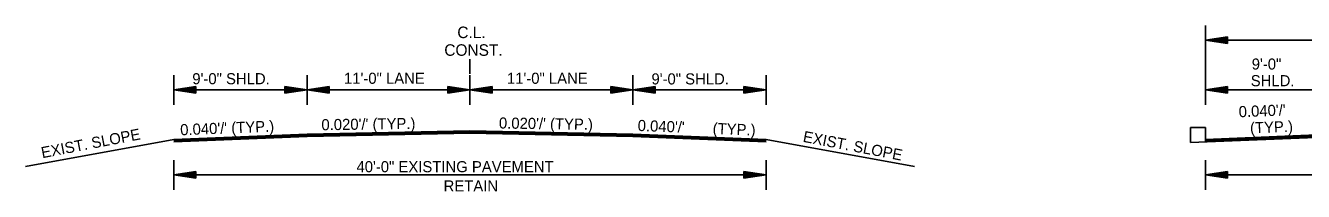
# Model space of a CAD drawing. Extents: x 545241 to 1930787, y -1971772 to 596640.
# Drawn here: x 546787 to 547650, y -1963232 to -1963120 of the extents above; entities that cross this region are included whole.
import ezdxf

# ---------------------------------------------------------------- set-up
doc = ezdxf.new("R2010")
doc.units = 0
doc.layers.add('R_Border', color=7, linetype='Continuous')
doc.layers.add('R_Draft', color=7, linetype='Continuous')

msp = doc.modelspace()

# ---------------------------------------------------------------- linework, layer by layer
at = {"layer": 'R_Border'}
for p, q in [((546977.57, -1963192.94), (546887.57, -1963196.54)), ((546977.57, -1963193.24), (546887.57, -1963196.84)), ((546977.57, -1963193.54), (546887.57, -1963197.14)), ((546977.57, -1963193.84), (546887.57, -1963197.44)), ((546977.57, -1963194.14), (546887.57, -1963197.74)), ((546977.57, -1963194.44), (546887.57, -1963198.04)), ((546977.57, -1963194.61), (546887.57, -1963198.21)), ((547197.57, -1963192.94), (547287.57, -1963196.54)), ((547197.57, -1963193.24), (547287.57, -1963196.84)), ((547197.57, -1963193.54), (547287.57, -1963197.14)), ((547197.57, -1963193.84), (547287.57, -1963197.44)), ((547197.57, -1963194.14), (547287.57, -1963197.74)), ((547197.57, -1963194.44), (547287.57, -1963198.04)), ((547197.57, -1963194.61), (547287.57, -1963198.21)), ((547573.95, -1963188.63), (547573.94, -1963198.62)), ((547674.12, -1963194.61), (547573.94, -1963198.61)), ((547584.12, -1963188.63), (547573.95, -1963188.63)), ((547584.12, -1963198.04), (547584.12, -1963188.63)), ((547674.12, -1963192.94), (547584.12, -1963196.54)), ((547674.12, -1963193.24), (547584.12, -1963196.84)), ((547674.12, -1963193.54), (547584.12, -1963197.14)), ((547674.12, -1963193.84), (547584.12, -1963197.44)), ((547674.12, -1963194.14), (547584.12, -1963197.74)), ((547674.12, -1963194.44), (547584.12, -1963198.04))]:
    msp.add_line(p, q, dxfattribs=at)
at = {"layer": 'R_Draft'}
for p, q in [((547584.12, -1963173.13), (547584.12, -1963119.59)), ((547599.12, -1963127.34), (547584.12, -1963129.59)), ((547584.12, -1963129.59), (547984.12, -1963129.59)), ((547599.12, -1963131.84), (547584.12, -1963129.59)), ((547599.12, -1963127.72), (547586.63, -1963129.59)), ((547599.12, -1963131.47), (547586.63, -1963129.59)), ((547599.12, -1963128.1), (547589.21, -1963129.59)), ((547599.12, -1963131.09), (547589.21, -1963129.59)), ((547599.12, -1963128.48), (547591.7, -1963129.59)), ((547599.12, -1963130.71), (547591.7, -1963129.59)), ((547599.12, -1963128.86), (547594.25, -1963129.59)), ((547599.12, -1963130.32), (547594.25, -1963129.59)), ((547599.12, -1963129.24), (547596.75, -1963129.59)), ((547599.12, -1963129.95), (547596.75, -1963129.59)), ((547599.12, -1963131.84), (547599.12, -1963127.34)), ((547087.57, -1963152.36), (547087.57, -1963142.36)), ((546887.57, -1963173.13), (546887.57, -1963153.13)), ((546902.57, -1963160.88), (546887.57, -1963163.13)), ((546902.57, -1963161.26), (546890.07, -1963163.13)), ((546902.57, -1963160.88), (546902.57, -1963165.38)), ((546962.57, -1963160.88), (546977.57, -1963163.13)), ((546962.57, -1963165.38), (546962.57, -1963160.88)), ((546962.57, -1963161.26), (546975.06, -1963163.13)), ((546977.57, -1963173.13), (546977.57, -1963153.24)), ((546992.57, -1963160.88), (546977.57, -1963163.13)), ((546992.57, -1963161.26), (546980.07, -1963163.13)), ((546992.57, -1963165.38), (546992.57, -1963160.88)), ((547072.57, -1963160.88), (547087.57, -1963163.13)), ((547072.57, -1963160.88), (547072.57, -1963165.38)), ((547072.57, -1963161.26), (547085.06, -1963163.13)), ((547087.57, -1963173.13), (547087.57, -1963153.24)), ((547102.57, -1963160.88), (547087.57, -1963163.13)), ((547102.57, -1963161.26), (547090.07, -1963163.13)), ((547102.57, -1963160.88), (547102.57, -1963165.38)), ((547182.57, -1963160.88), (547197.57, -1963163.13)), ((547182.57, -1963165.38), (547182.57, -1963160.88)), ((547182.57, -1963161.26), (547195.06, -1963163.13)), ((547197.57, -1963173.13), (547197.57, -1963153.24)), ((547212.57, -1963160.88), (547197.57, -1963163.13)), ((547212.57, -1963161.26), (547200.07, -1963163.13)), ((547212.57, -1963165.38), (547212.57, -1963160.88)), ((547272.57, -1963160.88), (547287.57, -1963163.13)), ((547272.57, -1963160.88), (547272.57, -1963165.38)), ((547272.57, -1963161.26), (547285.06, -1963163.13)), ((547287.57, -1963173.13), (547287.57, -1963153.13)), ((547599.12, -1963160.88), (547584.12, -1963163.13)), ((547599.12, -1963161.26), (547586.63, -1963163.13)), ((547599.12, -1963160.88), (547599.12, -1963165.38)), ((546977.57, -1963163.13), (546887.57, -1963163.13)), ((546902.57, -1963165.38), (546887.57, -1963163.13)), ((546902.57, -1963165.01), (546890.07, -1963163.13)), ((546902.57, -1963161.64), (546892.65, -1963163.13)), ((546902.57, -1963164.62), (546892.65, -1963163.13)), ((546902.57, -1963162.01), (546895.15, -1963163.13)), ((546902.57, -1963164.25), (546895.15, -1963163.13)), ((546902.57, -1963162.4), (546897.69, -1963163.13)), ((546902.57, -1963163.87), (546897.69, -1963163.13)), ((546902.57, -1963162.78), (546900.2, -1963163.13)), ((546902.57, -1963163.48), (546900.2, -1963163.13)), ((546962.57, -1963161.64), (546972.48, -1963163.13)), ((546962.57, -1963162.01), (546969.99, -1963163.13)), ((546962.57, -1963162.4), (546967.44, -1963163.13)), ((546962.57, -1963162.78), (546964.94, -1963163.13)), ((546962.57, -1963165.38), (546977.57, -1963163.13)), ((546962.57, -1963163.86), (546967.44, -1963163.13)), ((546962.57, -1963164.62), (546972.48, -1963163.13)), ((546962.57, -1963165.01), (546975.06, -1963163.13)), ((546962.57, -1963164.25), (546969.99, -1963163.13)), ((546962.57, -1963163.48), (546964.94, -1963163.13)), ((546992.57, -1963165.38), (546977.57, -1963163.13)), ((546977.57, -1963163.13), (547087.57, -1963163.13)), ((546992.57, -1963165.01), (546980.07, -1963163.13)), ((546992.57, -1963161.64), (546982.65, -1963163.13)), ((546992.57, -1963164.62), (546982.65, -1963163.13)), ((546992.57, -1963162.01), (546985.15, -1963163.13)), ((546992.57, -1963164.25), (546985.15, -1963163.13)), ((546992.57, -1963162.4), (546987.69, -1963163.13)), ((546992.57, -1963163.86), (546987.69, -1963163.13)), ((546992.57, -1963162.78), (546990.2, -1963163.13)), ((546992.57, -1963163.48), (546990.2, -1963163.13)), ((547072.57, -1963161.64), (547082.48, -1963163.13)), ((547072.57, -1963162.01), (547079.99, -1963163.13)), ((547072.57, -1963162.4), (547077.44, -1963163.13)), ((547072.57, -1963162.78), (547074.94, -1963163.13)), ((547072.57, -1963165.38), (547087.57, -1963163.13)), ((547072.57, -1963163.87), (547077.44, -1963163.13)), ((547072.57, -1963164.62), (547082.48, -1963163.13)), ((547072.57, -1963165.01), (547085.06, -1963163.13)), ((547072.57, -1963164.25), (547079.99, -1963163.13)), ((547072.57, -1963163.48), (547074.94, -1963163.13)), ((547197.57, -1963163.13), (547087.57, -1963163.13)), ((547102.57, -1963165.38), (547087.57, -1963163.13)), ((547102.57, -1963165.01), (547090.07, -1963163.13)), ((547102.57, -1963161.64), (547092.65, -1963163.13)), ((547102.57, -1963164.62), (547092.65, -1963163.13)), ((547102.57, -1963162.01), (547095.15, -1963163.13)), ((547102.57, -1963164.25), (547095.15, -1963163.13)), ((547102.57, -1963162.4), (547097.69, -1963163.13)), ((547102.57, -1963163.87), (547097.69, -1963163.13)), ((547102.57, -1963162.78), (547100.2, -1963163.13)), ((547102.57, -1963163.48), (547100.2, -1963163.13)), ((547182.57, -1963161.64), (547192.48, -1963163.13)), ((547182.57, -1963162.01), (547189.99, -1963163.13)), ((547182.57, -1963162.4), (547187.44, -1963163.13)), ((547182.57, -1963162.78), (547184.94, -1963163.13)), ((547182.57, -1963165.38), (547197.57, -1963163.13)), ((547182.57, -1963163.86), (547187.44, -1963163.13)), ((547182.57, -1963164.62), (547192.48, -1963163.13)), ((547182.57, -1963165.01), (547195.06, -1963163.13)), ((547182.57, -1963164.25), (547189.99, -1963163.13)), ((547182.57, -1963163.48), (547184.94, -1963163.13)), ((547197.57, -1963163.13), (547287.57, -1963163.13)), ((547212.57, -1963165.38), (547197.57, -1963163.13)), ((547212.57, -1963165.01), (547200.07, -1963163.13)), ((547212.57, -1963161.64), (547202.65, -1963163.13)), ((547212.57, -1963164.62), (547202.65, -1963163.13)), ((547212.57, -1963162.01), (547205.15, -1963163.13)), ((547212.57, -1963164.25), (547205.15, -1963163.13)), ((547212.57, -1963162.4), (547207.69, -1963163.13)), ((547212.57, -1963163.86), (547207.69, -1963163.13)), ((547212.57, -1963162.78), (547210.2, -1963163.13)), ((547212.57, -1963163.48), (547210.2, -1963163.13)), ((547272.57, -1963161.64), (547282.48, -1963163.13)), ((547272.57, -1963162.01), (547279.99, -1963163.13)), ((547272.57, -1963162.4), (547277.44, -1963163.13)), ((547272.57, -1963162.78), (547274.94, -1963163.13)), ((547272.57, -1963165.38), (547287.57, -1963163.13)), ((547272.57, -1963163.87), (547277.44, -1963163.13)), ((547272.57, -1963164.62), (547282.48, -1963163.13)), ((547272.57, -1963165.01), (547285.06, -1963163.13)), ((547272.57, -1963164.25), (547279.99, -1963163.13)), ((547272.57, -1963163.48), (547274.94, -1963163.13)), ((547674.12, -1963163.13), (547584.12, -1963163.13)), ((547599.12, -1963165.38), (547584.12, -1963163.13)), ((547599.12, -1963165.01), (547586.63, -1963163.13)), ((547599.12, -1963161.64), (547589.21, -1963163.13)), ((547599.12, -1963164.62), (547589.21, -1963163.13)), ((547599.12, -1963162.01), (547591.7, -1963163.13)), ((547599.12, -1963164.25), (547591.7, -1963163.13)), ((547599.12, -1963162.4), (547594.25, -1963163.13)), ((547599.12, -1963163.87), (547594.25, -1963163.13)), ((547599.12, -1963162.78), (547596.75, -1963163.13)), ((547599.12, -1963163.48), (547596.75, -1963163.13)), ((547087.57, -1963190.74), (546977.57, -1963192.94)), ((547087.56, -1963191.04), (546977.57, -1963193.24)), ((547087.57, -1963191.34), (546977.57, -1963193.54)), ((547087.59, -1963191.64), (546977.57, -1963193.84)), ((547087.59, -1963191.94), (546977.57, -1963194.14)), ((547087.6, -1963192.24), (546977.57, -1963194.44)), ((547087.6, -1963192.41), (546977.57, -1963194.61)), ((547087.53, -1963192.41), (547197.57, -1963194.61)), ((547087.54, -1963191.94), (547197.57, -1963194.14)), ((547087.54, -1963192.24), (547197.57, -1963194.44)), ((547087.55, -1963191.64), (547197.57, -1963193.84)), ((547087.56, -1963191.04), (547197.57, -1963193.24)), ((547087.56, -1963191.34), (547197.57, -1963193.54)), ((547087.57, -1963190.74), (547197.57, -1963192.94)), ((546887.57, -1963196.54), (546787.5, -1963214.91)), ((547287.57, -1963196.54), (547387.64, -1963214.91)), ((546887.57, -1963210.6), (546887.57, -1963230.6)), ((547287.57, -1963210.6), (547287.57, -1963230.6)), ((547584.12, -1963210.6), (547584.12, -1963230.6)), ((546902.57, -1963218.35), (546887.57, -1963220.6)), ((546887.57, -1963220.6), (547287.57, -1963220.6)), ((546902.57, -1963222.85), (546887.57, -1963220.6)), ((546902.57, -1963218.72), (546890.07, -1963220.6)), ((546902.57, -1963222.47), (546890.07, -1963220.6)), ((546902.57, -1963219.1), (546892.65, -1963220.6)), ((546902.57, -1963222.09), (546892.65, -1963220.6)), ((546902.57, -1963219.48), (546895.15, -1963220.6)), ((546902.57, -1963221.71), (546895.15, -1963220.6)), ((546902.57, -1963219.86), (546897.69, -1963220.6)), ((546902.57, -1963221.32), (546897.69, -1963220.6)), ((546902.57, -1963220.24), (546900.2, -1963220.6)), ((546902.57, -1963220.95), (546900.2, -1963220.6)), ((546902.57, -1963222.85), (546902.57, -1963218.35)), ((547272.57, -1963218.35), (547287.57, -1963220.6)), ((547272.57, -1963218.35), (547272.57, -1963222.85)), ((547272.57, -1963218.72), (547285.06, -1963220.6)), ((547272.57, -1963219.1), (547282.48, -1963220.6)), ((547272.57, -1963219.48), (547279.99, -1963220.6)), ((547272.57, -1963219.87), (547277.44, -1963220.6)), ((547272.57, -1963220.24), (547274.94, -1963220.6)), ((547272.57, -1963222.85), (547287.57, -1963220.6)), ((547272.57, -1963221.33), (547277.44, -1963220.6)), ((547272.57, -1963222.09), (547282.48, -1963220.6)), ((547272.57, -1963222.47), (547285.06, -1963220.6)), ((547272.57, -1963221.71), (547279.99, -1963220.6)), ((547272.57, -1963220.95), (547274.94, -1963220.6)), ((547599.12, -1963218.35), (547584.12, -1963220.6)), ((547584.12, -1963220.6), (547984.12, -1963220.6)), ((547599.12, -1963222.85), (547584.12, -1963220.6)), ((547599.12, -1963218.72), (547586.63, -1963220.6)), ((547599.12, -1963222.47), (547586.63, -1963220.6)), ((547599.12, -1963219.1), (547589.21, -1963220.6)), ((547599.12, -1963222.09), (547589.21, -1963220.6)), ((547599.12, -1963219.48), (547591.7, -1963220.6)), ((547599.12, -1963221.71), (547591.7, -1963220.6)), ((547599.12, -1963219.86), (547594.25, -1963220.6)), ((547599.12, -1963221.32), (547594.25, -1963220.6)), ((547599.12, -1963220.24), (547596.75, -1963220.6)), ((547599.12, -1963220.95), (547596.75, -1963220.6)), ((547599.12, -1963222.85), (547599.12, -1963218.35))]:
    msp.add_line(p, q, dxfattribs=at)

# ---------------------------------------------------------------- texts
for s, height, p in [('C.L.', 7.8, (547079.03, -1963128.11)), ('CONST.', 7.8, (547070.24, -1963140.07)), ('9\'-0"', 7.5, (547615.39, -1963149.38)), ('9\'-0" SHLD.', 7.5, (546900.09, -1963159.29)), ('11\'-0" LANE', 7.5, (547002.51, -1963159)), ('11\'-0" LANE', 7.5, (547112.51, -1963159)), ('9\'-0" SHLD.', 7.5, (547210.09, -1963159.42)), ('SHLD.', 7.5, (547614.71, -1963160.63)), ('40\'-0" EXISTING PAVEMENT', 7.5, (547010.94, -1963218.76)), ('RETAIN', 7.5, (547069.76, -1963231.77))]:
    msp.add_text(s, height=height, dxfattribs=at).set_placement(p)
for s, rotation, p in [("0.040'/' ", 2.29061, (547606.73, -1963181.62)), ("0.040'/' (TYP.)", 2.29061, (546892.06, -1963193.82)), ("0.020'/' (TYP.)", 0.87191, (546987.31, -1963190.42)), ("0.020'/' (TYP.)", 359.12809, (547107.06, -1963189.19)), ("0.040'/' ", 357.70939, (547200.68, -1963190.82)), ('(TYP.)', 357.70939, (547251.31, -1963192.84)), ('(TYP.)', 2.29061, (547614.37, -1963192.58)), ('EXIST. SLOPE', 10.88286, (546798.8, -1963209.32)), ('EXIST. SLOPE', 349.11714, (547311.95, -1963198.13))]:
    msp.add_text(s, height=7.5, rotation=rotation, dxfattribs=at).set_placement(p)

doc.saveas('drawing.dxf')
